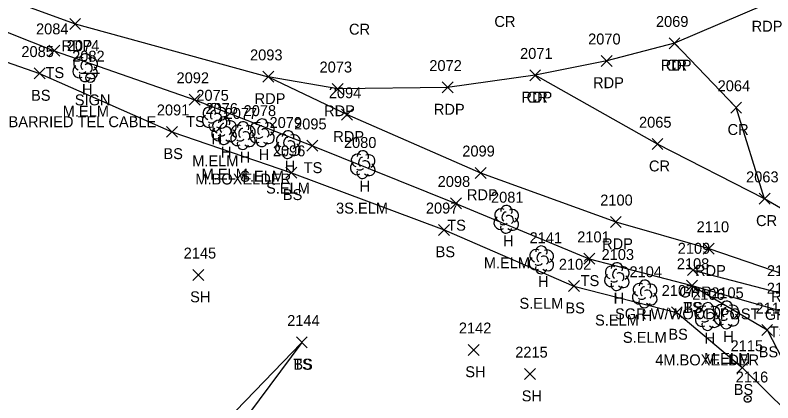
# Model space of a CAD drawing. Extents: x 1459992 to 1461532, y 647785 to 648535.
# Drawn here: x 1461117.9 to 1461256.6, y 648209.9 to 648280.9 of the extents above; entities that cross this region are included whole.
import ezdxf

# ---------------------------------------------------------------- set-up
doc = ezdxf.new("R2010")
doc.units = 0
for name, color, linetype in [('L_A', 7, 'Continuous'), ('L_C', 7, 'Continuous'), ('L_I', 7, 'Continuous'), ('L_TIC', 7, 'Continuous'), ('LELB', 7, 'Continuous'), ('LTD', 7, 'Continuous'), ('P_A', 7, 'Continuous'), ('P_I', 7, 'Continuous'), ('P_TIC', 7, 'Continuous'), ('PET', 7, 'Continuous'), ('PRC', 7, 'Continuous'), ('R_A', 7, 'Continuous'), ('R_C', 7, 'Continuous'), ('R_I', 7, 'Continuous'), ('R_TIC', 7, 'Continuous'), ('RGR', 7, 'Continuous'), ('S_A', 7, 'Continuous'), ('S_C', 7, 'Continuous'), ('S_I', 7, 'Continuous'), ('SSGN', 7, 'Continuous'), ('U_I', 7, 'Continuous'), ('UPGW', 7, 'Continuous')]:
    doc.layers.add(name, color=color, linetype=linetype)

msp = doc.modelspace()

# ---------------------------------------------------------------- linework, layer by layer
at = {"layer": 'L_TIC'}
for points in [[(1461124.02, 648273.34), (1461126.02, 648275.34)], [(1461126.02, 648273.34), (1461124.02, 648275.34)], [(1461121.33, 648269.19), (1461123.33, 648271.19)], [(1461123.33, 648269.19), (1461121.33, 648271.19)], [(1461149.75, 648264.39), (1461151.75, 648266.39)], [(1461151.75, 648264.39), (1461149.75, 648266.39)], [(1461145.57, 648258.51), (1461147.57, 648260.51)], [(1461147.57, 648258.51), (1461145.57, 648260.51)], [(1461171.28, 648255.95), (1461173.28, 648257.95)], [(1461173.28, 648255.95), (1461171.28, 648257.95)], [(1461167.44, 648251.02), (1461169.44, 648253.02)], [(1461169.44, 648251.02), (1461167.44, 648253.02)], [(1461197.57, 648245.42), (1461199.57, 648247.42)], [(1461199.57, 648245.42), (1461197.57, 648247.42)], [(1461195.41, 648240.56), (1461197.41, 648242.56)], [(1461197.41, 648240.56), (1461195.41, 648242.56)], [(1461222, 648235.28), (1461224, 648237.28)], [(1461224, 648235.28), (1461222, 648237.28)], [(1461150.42, 648232.32), (1461152.42, 648234.32)], [(1461152.42, 648232.32), (1461150.42, 648234.32)], [(1461219.18, 648230.28), (1461221.18, 648232.28)], [(1461221.18, 648230.28), (1461219.18, 648232.28)], [(1461240.79, 648230.37), (1461242.79, 648232.37)], [(1461242.79, 648230.37), (1461240.79, 648232.37)], [(1461240.79, 648230.37), (1461242.79, 648232.37)], [(1461242.79, 648230.37), (1461240.79, 648232.37)], [(1461238.03, 648225.47), (1461240.03, 648227.47)], [(1461240.03, 648225.47), (1461238.03, 648227.47)], [(1461254.57, 648222.25), (1461256.57, 648224.25)], [(1461256.57, 648222.25), (1461254.57, 648224.25)], [(1461169.36, 648219.98), (1461171.36, 648221.98)], [(1461171.36, 648219.98), (1461169.36, 648221.98)], [(1461169.36, 648219.98), (1461171.36, 648221.98)], [(1461171.36, 648219.98), (1461169.36, 648221.98)], [(1461200.8, 648218.61), (1461202.8, 648220.61)], [(1461202.8, 648218.61), (1461200.8, 648220.61)], [(1461250, 648215.36), (1461252, 648217.36)], [(1461252, 648215.36), (1461250, 648217.36)], [(1461211.13, 648214.19), (1461213.13, 648216.19)], [(1461213.13, 648214.19), (1461211.13, 648216.19)]]:
    msp.add_lwpolyline(points, dxfattribs=at)
at = {"layer": 'LELB'}
for points in [[(1460941.15, 648349.78), (1460973.92, 648337.2), (1461015.24, 648321.11), (1461040.67, 648310.01), (1461064.18, 648298.16), (1461082.22, 648291.36), (1461125.02, 648274.34), (1461150.75, 648265.39), (1461172.28, 648256.95), (1461198.57, 648246.42), (1461223, 648236.28), (1461241.79, 648231.37), (1461257.62, 648226.89), (1461266.9, 648221.63), (1461276.01, 648214.68), (1461281.47, 648211.06), (1461286.34, 648210.46)], [(1460939.64, 648344.38), (1460971.19, 648332.05), (1461013, 648314.77), (1461039.31, 648304.76), (1461062.9, 648294.47), (1461067.87, 648294.36), (1461073.92, 648287.11), (1461122.33, 648270.19), (1461146.57, 648259.51), (1461168.44, 648252.02), (1461196.41, 648241.56), (1461220.18, 648231.28), (1461239.03, 648226.47), (1461251, 648216.36), (1461259.3, 648208.22), (1461262.9, 648204.94)], [(1461241.79, 648231.37), (1461255.57, 648223.25), (1461261.15, 648212.52)], [(1461170.36, 648220.98), (1461142.74, 648192.43), (1461120.86, 648163.3), (1461094.01, 648129.04), (1461070.6, 648103.29)], [(1461170.36, 648220.98), (1461146.74, 648189.22), (1461125.11, 648160.77), (1461098.02, 648125.46), (1461077.7, 648098.65)]]:
    msp.add_lwpolyline(points, dxfattribs=at)
at = {"layer": 'LTD'}
for p, q in [((1461130.66, 648271.28), (1461130.66, 648271.28)), ((1461130.66, 648271.28), (1461130.66, 648271.28)), ((1461154.37, 648262.19), (1461154.37, 648262.19)), ((1461154.37, 648262.19), (1461154.37, 648262.19)), ((1461156.1, 648259.77), (1461156.1, 648259.77)), ((1461156.1, 648259.77), (1461156.1, 648259.77)), ((1461163.03, 648259.38), (1461163.03, 648259.38)), ((1461163.03, 648259.38), (1461163.03, 648259.38)), ((1461159.56, 648258.87), (1461159.56, 648258.87)), ((1461159.56, 648258.87), (1461159.56, 648258.87)), ((1461167.78, 648257.21), (1461167.78, 648257.21)), ((1461167.78, 648257.21), (1461167.78, 648257.21)), ((1461181.49, 648253.55), (1461181.49, 648253.55)), ((1461181.49, 648253.55), (1461181.49, 648253.55)), ((1461207.77, 648243.54), (1461207.77, 648243.54)), ((1461207.77, 648243.54), (1461207.77, 648243.54)), ((1461214.18, 648236.13), (1461214.18, 648236.13)), ((1461214.18, 648236.13), (1461214.18, 648236.13)), ((1461228.02, 648233.06), (1461228.02, 648233.06)), ((1461228.02, 648233.06), (1461228.02, 648233.06)), ((1461233.12, 648229.9), (1461233.12, 648229.9)), ((1461233.12, 648229.9), (1461233.12, 648229.9)), ((1461248.09, 648226.05), (1461248.09, 648226.05)), ((1461248.09, 648226.05), (1461248.09, 648226.05)), ((1461244.66, 648225.77), (1461244.66, 648225.77)), ((1461244.66, 648225.77), (1461244.66, 648225.77))]:
    msp.add_line(p, q, dxfattribs=at)
for centre in [(1461130.7, 648272.72), (1461154.42, 648263.63), (1461156.14, 648261.2), (1461159.61, 648260.31), (1461163.07, 648260.82), (1461167.83, 648258.65), (1461181.53, 648254.99), (1461207.82, 648244.97), (1461214.23, 648237.57), (1461228.06, 648234.49), (1461233.17, 648231.33), (1461244.71, 648227.21), (1461248.14, 648227.48)]:
    msp.add_arc(centre, 1.05, 335.5272, 180.9563, dxfattribs=at)
for centre, major_axis, ratio, start_param, end_param in [((1461129.86, 648271.95), (1.21, -0.51), 0.895232, 1.570796, 4.712389), ((1461131.7, 648271.87), (-1.14, -0.48), 0.949671, 1.570796, 4.712389), ((1461130.45, 648271.74), (-0.208, -0.792), 0.645439, 3.141593, 6.283185), ((1461131.16, 648271.12), (-0.5, 0.667), 0.989748, 3.141593, 6.283185), ((1461129.57, 648270.57), (0.58, -1.04), 0.959034, 3.141593, 6.283185), ((1461130.2, 648270.53), (-0.625, -0.083), 0.423636, 0, 3.141593), ((1461131.66, 648270.45), (-1.09, 0.79), 0.841452, 1.570796, 4.712389), ((1461130.66, 648269.78), (0.26, 1.06), 0.942809, 1.570796, 4.712389), ((1461153.58, 648262.86), (1.21, -0.51), 0.895232, 1.570796, 4.712389), ((1461154.16, 648262.65), (-0.208, -0.792), 0.645439, 3.141593, 6.283185), ((1461155.41, 648262.78), (-1.14, -0.48), 0.949671, 1.570796, 4.712389), ((1461153.29, 648261.48), (0.58, -1.04), 0.959034, 3.141593, 6.283185), ((1461154.87, 648262.03), (-0.5, 0.667), 0.989748, 3.141593, 6.283185), ((1461155.37, 648261.36), (-1.09, 0.79), 0.841452, 1.570796, 4.712389), ((1461154.37, 648260.69), (0.26, 1.06), 0.942809, 1.570796, 4.712389), ((1461153.91, 648261.44), (-0.625, -0.083), 0.423636, 0, 3.141593), ((1461155.31, 648260.43), (1.21, -0.51), 0.895232, 1.570796, 4.712389), ((1461155.89, 648260.22), (-0.208, -0.792), 0.645439, 3.141593, 6.283185), ((1461157.14, 648260.35), (-1.14, -0.48), 0.949671, 1.570796, 4.712389), ((1461158.77, 648259.54), (1.21, -0.51), 0.895232, 1.570796, 4.712389), ((1461160.6, 648259.46), (-1.14, -0.48), 0.949671, 1.570796, 4.712389), ((1461162.24, 648260.05), (1.21, -0.51), 0.895232, 1.570796, 4.712389), ((1461162.82, 648259.84), (-0.208, -0.792), 0.645439, 3.141593, 6.283185), ((1461164.07, 648259.97), (-1.14, -0.48), 0.949671, 1.570796, 4.712389), ((1461155.01, 648259.06), (0.58, -1.04), 0.959034, 3.141593, 6.283185), ((1461156.6, 648259.6), (-0.5, 0.667), 0.989748, 3.141593, 6.283185), ((1461157.1, 648258.93), (-1.09, 0.79), 0.841452, 1.570796, 4.712389), ((1461159.35, 648259.33), (-0.208, -0.792), 0.645439, 3.141593, 6.283185), ((1461160.06, 648258.71), (-0.5, 0.667), 0.989748, 3.141593, 6.283185), ((1461161.94, 648258.68), (0.58, -1.04), 0.959034, 3.141593, 6.283185), ((1461163.53, 648259.22), (-0.5, 0.667), 0.989748, 3.141593, 6.283185), ((1461164.03, 648258.55), (-1.09, 0.79), 0.841452, 1.570796, 4.712389), ((1461156.1, 648258.27), (0.26, 1.06), 0.942809, 1.570796, 4.712389), ((1461155.64, 648259.01), (-0.625, -0.083), 0.423636, 0, 3.141593), ((1461158.48, 648258.16), (0.58, -1.04), 0.959034, 3.141593, 6.283185), ((1461159.1, 648258.12), (-0.625, -0.083), 0.423636, 0, 3.141593), ((1461160.56, 648258.04), (-1.09, 0.79), 0.841452, 1.570796, 4.712389), ((1461163.03, 648257.88), (0.26, 1.06), 0.942809, 1.570796, 4.712389), ((1461162.57, 648258.63), (-0.625, -0.083), 0.423636, 0, 3.141593), ((1461166.99, 648257.88), (1.21, -0.51), 0.895232, 1.570796, 4.712389), ((1461167.57, 648257.67), (-0.208, -0.792), 0.645439, 3.141593, 6.283185), ((1461168.28, 648257.05), (-0.5, 0.667), 0.989748, 3.141593, 6.283185), ((1461168.82, 648257.8), (-1.14, -0.48), 0.949671, 1.570796, 4.712389), ((1461159.56, 648257.37), (0.26, 1.06), 0.942809, 1.570796, 4.712389), ((1461166.7, 648256.5), (0.58, -1.04), 0.959034, 3.141593, 6.283185), ((1461167.32, 648256.46), (-0.625, -0.083), 0.423636, 0, 3.141593), ((1461168.78, 648256.38), (-1.09, 0.79), 0.841452, 1.570796, 4.712389), ((1461167.78, 648255.71), (0.26, 1.06), 0.942809, 1.570796, 4.712389), ((1461180.7, 648254.22), (1.21, -0.51), 0.895232, 1.570796, 4.712389), ((1461182.53, 648254.14), (-1.14, -0.48), 0.949671, 1.570796, 4.712389), ((1461180.4, 648252.84), (0.58, -1.04), 0.959034, 3.141593, 6.283185), ((1461181.28, 648254.01), (-0.208, -0.792), 0.645439, 3.141593, 6.283185), ((1461181.99, 648253.39), (-0.5, 0.667), 0.989748, 3.141593, 6.283185), ((1461181.03, 648252.8), (-0.625, -0.083), 0.423636, 0, 3.141593), ((1461182.49, 648252.72), (-1.09, 0.79), 0.841452, 1.570796, 4.712389), ((1461181.49, 648252.05), (0.26, 1.06), 0.942809, 1.570796, 4.712389), ((1461206.98, 648244.21), (1.21, -0.51), 0.895232, 1.570796, 4.712389), ((1461208.81, 648244.12), (-1.14, -0.48), 0.949671, 1.570796, 4.712389), ((1461207.56, 648244), (-0.208, -0.792), 0.645439, 3.141593, 6.283185), ((1461208.27, 648243.37), (-0.5, 0.667), 0.989748, 3.141593, 6.283185), ((1461206.69, 648242.83), (0.58, -1.04), 0.959034, 3.141593, 6.283185), ((1461207.31, 648242.79), (-0.625, -0.083), 0.423636, 0, 3.141593), ((1461208.77, 648242.71), (-1.09, 0.79), 0.841452, 1.570796, 4.712389), ((1461207.77, 648242.04), (0.26, 1.06), 0.942809, 1.570796, 4.712389), ((1461213.39, 648236.8), (1.21, -0.51), 0.895232, 1.570796, 4.712389), ((1461213.97, 648236.59), (-0.208, -0.792), 0.645439, 3.141593, 6.283185), ((1461215.22, 648236.71), (-1.14, -0.48), 0.949671, 1.570796, 4.712389), ((1461213.1, 648235.42), (0.58, -1.04), 0.959034, 3.141593, 6.283185), ((1461214.68, 648235.96), (-0.5, 0.667), 0.989748, 3.141593, 6.283185), ((1461215.18, 648235.3), (-1.09, 0.79), 0.841452, 1.570796, 4.712389), ((1461214.18, 648234.63), (0.26, 1.06), 0.942809, 1.570796, 4.712389), ((1461213.72, 648235.38), (-0.625, -0.083), 0.423636, 0, 3.141593), ((1461227.22, 648233.73), (1.21, -0.51), 0.895232, 1.570796, 4.712389), ((1461227.81, 648233.52), (-0.208, -0.792), 0.645439, 3.141593, 6.283185), ((1461229.06, 648233.64), (-1.14, -0.48), 0.949671, 1.570796, 4.712389), ((1461226.93, 648232.35), (0.58, -1.04), 0.959034, 3.141593, 6.283185), ((1461228.52, 648232.89), (-0.5, 0.667), 0.989748, 3.141593, 6.283185), ((1461229.02, 648232.23), (-1.09, 0.79), 0.841452, 1.570796, 4.712389), ((1461228.02, 648231.56), (0.26, 1.06), 0.942809, 1.570796, 4.712389), ((1461227.56, 648232.31), (-0.625, -0.083), 0.423636, 0, 3.141593), ((1461232.33, 648230.57), (1.21, -0.51), 0.895232, 1.570796, 4.712389), ((1461234.16, 648230.48), (-1.14, -0.48), 0.949671, 1.570796, 4.712389), ((1461232.04, 648229.19), (0.58, -1.04), 0.959034, 3.141593, 6.283185), ((1461232.91, 648230.36), (-0.208, -0.792), 0.645439, 3.141593, 6.283185), ((1461233.62, 648229.73), (-0.5, 0.667), 0.989748, 3.141593, 6.283185), ((1461232.66, 648229.15), (-0.625, -0.083), 0.423636, 0, 3.141593), ((1461234.12, 648229.07), (-1.09, 0.79), 0.841452, 1.570796, 4.712389), ((1461233.12, 648228.4), (0.26, 1.06), 0.942809, 1.570796, 4.712389), ((1461243.87, 648226.44), (1.21, -0.51), 0.895232, 1.570796, 4.712389), ((1461245.71, 648226.36), (-1.14, -0.48), 0.949671, 1.570796, 4.712389), ((1461247.3, 648226.71), (1.21, -0.51), 0.895232, 1.570796, 4.712389), ((1461247.88, 648226.51), (-0.208, -0.792), 0.645439, 3.141593, 6.283185), ((1461249.13, 648226.63), (-1.14, -0.48), 0.949671, 1.570796, 4.712389), ((1461243.58, 648225.06), (0.58, -1.04), 0.959034, 3.141593, 6.283185), ((1461244.46, 648226.23), (-0.208, -0.792), 0.645439, 3.141593, 6.283185), ((1461245.16, 648225.61), (-0.5, 0.667), 0.989748, 3.141593, 6.283185), ((1461247.01, 648225.34), (0.58, -1.04), 0.959034, 3.141593, 6.283185), ((1461248.59, 648225.88), (-0.5, 0.667), 0.989748, 3.141593, 6.283185), ((1461249.09, 648225.21), (-1.09, 0.79), 0.841452, 1.570796, 4.712389), ((1461244.21, 648225.02), (-0.625, -0.083), 0.423636, 0, 3.141593), ((1461245.66, 648224.94), (-1.09, 0.79), 0.841452, 1.570796, 4.712389), ((1461248.09, 648224.55), (0.26, 1.06), 0.942809, 1.570796, 4.712389), ((1461247.63, 648225.3), (-0.625, -0.083), 0.423636, 0, 3.141593), ((1461244.66, 648224.27), (0.26, 1.06), 0.942809, 1.570796, 4.712389)]:
    msp.add_ellipse(centre, major_axis=major_axis, ratio=ratio, start_param=start_param, end_param=end_param, dxfattribs=at)
at = {"layer": 'P_TIC'}
for points in [[(1461127.85, 648278.26), (1461129.85, 648280.26)], [(1461129.85, 648278.26), (1461127.85, 648280.26)], [(1461237.6, 648274.7), (1461239.6, 648276.7)], [(1461239.6, 648274.7), (1461237.6, 648276.7)], [(1461237.6, 648274.7), (1461239.6, 648276.7)], [(1461239.6, 648274.7), (1461237.6, 648276.7)], [(1461225.2, 648271.49), (1461227.2, 648273.49)], [(1461227.2, 648271.49), (1461225.2, 648273.49)], [(1461163.21, 648268.58), (1461165.21, 648270.58)], [(1461165.21, 648268.58), (1461163.21, 648270.58)], [(1461163.21, 648268.58), (1461165.21, 648270.58)], [(1461165.21, 648268.58), (1461163.21, 648270.58)], [(1461212.09, 648268.85), (1461214.09, 648270.85)], [(1461214.09, 648268.85), (1461212.09, 648270.85)], [(1461212.09, 648268.85), (1461214.09, 648270.85)], [(1461214.09, 648268.85), (1461212.09, 648270.85)], [(1461175.94, 648266.36), (1461177.94, 648268.36)], [(1461177.94, 648266.36), (1461175.94, 648268.36)], [(1461196.04, 648266.63), (1461198.04, 648268.63)], [(1461198.04, 648266.63), (1461196.04, 648268.63)], [(1461248.89, 648262.93), (1461250.89, 648264.93)], [(1461250.89, 648262.93), (1461248.89, 648264.93)], [(1461177.63, 648261.65), (1461179.63, 648263.65)], [(1461179.63, 648261.65), (1461177.63, 648263.65)], [(1461234.48, 648256.26), (1461236.48, 648258.26)], [(1461236.48, 648256.26), (1461234.48, 648258.26)], [(1461202.09, 648250.99), (1461204.09, 648252.99)], [(1461204.09, 648250.99), (1461202.09, 648252.99)], [(1461254.1, 648246.26), (1461256.1, 648248.26)], [(1461256.1, 648246.26), (1461254.1, 648248.26)], [(1461254.1, 648246.26), (1461256.1, 648248.26)], [(1461256.1, 648246.26), (1461254.1, 648248.26)], [(1461226.86, 648242.02), (1461228.86, 648244.02)], [(1461228.86, 648242.02), (1461226.86, 648244.02)], [(1461243.86, 648237.13), (1461245.86, 648239.13)], [(1461245.86, 648237.13), (1461243.86, 648239.13)]]:
    msp.add_lwpolyline(points, dxfattribs=at)
at = {"layer": 'PET'}
for points in [[(1461431.71, 648423.56), (1461406.61, 648408.47), (1461395.32, 648400.74), (1461379.71, 648387.97), (1461360, 648370.89), (1461342.5, 648355.32), (1461322.76, 648336.16), (1461306.54, 648318.18), (1461292.23, 648305.65), (1461275.7, 648293.86), (1461255.23, 648282.83), (1461238.6, 648275.7), (1461226.2, 648272.49), (1461213.09, 648269.85), (1461197.04, 648267.63), (1461176.94, 648267.36), (1461164.21, 648269.58)], [(1460942.85, 648353.98), (1460975.34, 648340.07), (1461016.08, 648323.29), (1461041.44, 648312.66), (1461070.03, 648301.09), (1461083.95, 648295.62), (1461128.85, 648279.26), (1461164.21, 648269.58), (1461178.63, 648262.65), (1461203.09, 648251.99), (1461227.86, 648243.02), (1461244.86, 648238.13), (1461258.8, 648233.38), (1461270.23, 648226.19), (1461279.65, 648219.62), (1461287.61, 648211.81)]]:
    msp.add_lwpolyline(points, dxfattribs=at)
at = {"layer": 'PRC'}
for points in [[(1461255.1, 648247.26), (1461249.89, 648263.93), (1461238.6, 648275.7)], [(1461267.85, 648239.79), (1461255.1, 648247.26), (1461235.48, 648257.26), (1461213.09, 648269.85)]]:
    msp.add_lwpolyline(points, dxfattribs=at)
at = {"layer": 'R_TIC'}
for points in [[(1461240.97, 648233.2), (1461242.97, 648235.2)], [(1461242.97, 648233.2), (1461240.97, 648235.2)]]:
    msp.add_lwpolyline(points, dxfattribs=at)
at = {"layer": 'RGR'}
msp.add_lwpolyline([(1461241.97, 648234.2), (1461257.65, 648230.1), (1461269.1, 648224.37), (1461278.11, 648218.35), (1461287.31, 648211.6)], dxfattribs=at)
at = {"layer": 'SSGN'}
for p, q in [((1461130, 648270.21), (1461133.33, 648270.21)), ((1461131.64, 648269.38), (1461131.64, 648269.38))]:
    msp.add_line(p, q, dxfattribs=at)
msp.add_circle((1461131.64, 648269.38), 0.833, dxfattribs=at)
at = {"layer": 'UPGW'}
for radius in [0.625, 0.0833]:
    msp.add_circle((1461251.99, 648210.64), radius, dxfattribs=at)

# ---------------------------------------------------------------- texts
at = {"layer": 'L_A'}
for s, p in [('TS', (1461123.42, 648269.34)), ('H', (1461130.09, 648266.28)), ('BS', (1461120.77, 648265.19)), ('TS', (1461149.16, 648260.39)), ('H', (1461153.81, 648257.19)), ('BS', (1461145.01, 648254.51)), ('H', (1461155.53, 648254.77)), ('H', (1461158.99, 648253.87)), ('H', (1461162.46, 648254.38)), ('H', (1461167.21, 648252.21)), ('TS', (1461170.69, 648251.95)), ('H', (1461180.92, 648248.55)), ('BS', (1461166.88, 648247.02)), ('TS', (1461196.98, 648241.42)), ('H', (1461207.2, 648238.54)), ('BS', (1461194.85, 648236.56)), ('H', (1461213.62, 648231.13)), ('TS', (1461221.41, 648231.28)), ('SH', (1461149.9, 648228.32)), ('H', (1461227.45, 648228.06)), ('BS', (1461218.62, 648226.28)), ('TS', (1461240.2, 648226.37)), ('BS', (1461240.23, 648226.37)), ('H', (1461232.56, 648224.9)), ('BS', (1461237.47, 648221.47)), ('TS', (1461256.03, 648221.89)), ('H', (1461244.1, 648220.77)), ('H', (1461247.52, 648221.05)), ('BS', (1461254.01, 648218.25)), ('TS', (1461168.77, 648215.98)), ('BS', (1461168.8, 648215.98)), ('SH', (1461200.29, 648214.61)), ('SH', (1461210.62, 648210.19)), ('BS', (1461249.44, 648211.36))]:
    msp.add_text(s, height=2, dxfattribs=at).set_placement(p)
at = {"layer": 'L_C'}
for s, p in [('M.ELM', (1461126.56, 648262.28)), ('M.ELM', (1461150.28, 648253.19)), ('M.ELM', (1461152, 648250.77)), ('S.ELM', (1461159.06, 648250.38)), ('M.BOXELDER', (1461150.86, 648249.87)), ('S.ELM', (1461163.81, 648248.21)), ('3S.ELM', (1461176.62, 648244.55)), ('M.ELM', (1461203.68, 648234.54)), ('S.ELM', (1461210.21, 648227.13)), ('S.ELM', (1461224.05, 648224.06)), ('S.ELM', (1461229.15, 648220.9)), ('M.ELM', (1461244, 648217.05)), ('4M.BOXELDER', (1461235.07, 648216.77))]:
    msp.add_text(s, height=2, dxfattribs=at).set_placement(p)
at = {"layer": 'L_I'}
for s, p in [('2084', (1461121.68, 648277.34)), ('2074', (1461127.32, 648274.28)), ('2085', (1461119, 648273.19)), ('2092', (1461147.41, 648268.39)), ('2075', (1461151.03, 648265.19)), ('2091', (1461143.8, 648262.51)), ('2076', (1461152.7, 648262.77)), ('2077', (1461156.22, 648261.87)), ('2078', (1461159.69, 648262.38)), ('2079', (1461164.44, 648260.21)), ('2095', (1461168.94, 648259.95)), ('2080', (1461178.06, 648256.55)), ('2096', (1461165.04, 648255.02)), ('2098', (1461195.23, 648249.42)), ('2081', (1461205, 648246.54)), ('2097', (1461193.07, 648244.56)), ('2101', (1461220.79, 648239.28)), ('2141', (1461212.06, 648239.13)), ('2145', (1461148.72, 648236.32)), ('2103', (1461225.24, 648236.06)), ('2102', (1461217.41, 648234.28)), ('2108', (1461239.02, 648234.37)), ('2108', (1461239.02, 648234.37)), ('2104', (1461230.35, 648232.9)), ('2113', (1461255.5, 648229.89)), ('2107', (1461236.25, 648229.47)), ('2106', (1461241.84, 648228.77)), ('2105', (1461245.32, 648229.05)), ('2114', (1461253.44, 648226.25)), ('2144', (1461167.67, 648223.98)), ('2144', (1461167.67, 648223.98)), ('2142', (1461199.11, 648222.61)), ('2115', (1461248.87, 648219.36)), ('2215', (1461209.43, 648218.19))]:
    msp.add_text(s, height=2, dxfattribs=at).set_placement(p)
at = {"layer": 'P_A'}
for s, p in [('CR', (1461205.61, 648278.7)), ('CR', (1461178.99, 648277.29)), ('RDP', (1461252.72, 648277.83)), ('RDP', (1461126.34, 648274.26)), ('RDP', (1461236.08, 648270.7)), ('CR', (1461237.03, 648270.7)), ('RDP', (1461223.69, 648267.49)), ('RDP', (1461161.7, 648264.58)), ('RDP', (1461161.7, 648264.58)), ('RDP', (1461210.57, 648264.85)), ('CR', (1461211.52, 648264.85)), ('RDP', (1461174.43, 648262.36)), ('RDP', (1461194.53, 648262.63)), ('CR', (1461248.32, 648258.93)), ('RDP', (1461176.11, 648257.65)), ('CR', (1461233.92, 648252.26)), ('RDP', (1461200.58, 648246.99)), ('CR', (1461253.53, 648242.26)), ('CR', (1461253.53, 648242.26)), ('RDP', (1461225.34, 648238.02)), ('RDP', (1461242.35, 648233.13)), ('RDP', (1461256.29, 648228.38))]:
    msp.add_text(s, height=2, dxfattribs=at).set_placement(p)
at = {"layer": 'P_I'}
for s, p in [('2069', (1461235.2, 648278.7)), ('2069', (1461235.2, 648278.7)), ('2070', (1461222.78, 648275.49)), ('2093', (1461160.87, 648272.58)), ('2093', (1461160.87, 648272.58)), ('2071', (1461210.32, 648272.85)), ('2071', (1461210.32, 648272.85)), ('2073', (1461173.6, 648270.36)), ('2072', (1461193.7, 648270.63)), ('2094', (1461175.29, 648265.65)), ('2064', (1461246.5, 648266.93)), ('2065', (1461232.1, 648260.26)), ('2099', (1461199.74, 648254.99)), ('2063', (1461251.71, 648250.26)), ('2063', (1461251.71, 648250.26)), ('2100', (1461225, 648246.02)), ('2110', (1461242.65, 648241.13))]:
    msp.add_text(s, height=2, dxfattribs=at).set_placement(p)
at = {"layer": 'R_A'}
for p in [(1461239.46, 648229.2), (1461255.14, 648225.1)]:
    msp.add_text('GRR', height=2, dxfattribs=at).set_placement(p)
at = {"layer": 'R_C'}
msp.add_text('SGR W/WOOD POST', height=2, dxfattribs=at).set_placement((1461227.71, 648225.2))
at = {"layer": 'R_I'}
for s, p in [('2109', (1461239.19, 648237.2)), ('2112', (1461255.53, 648233.1))]:
    msp.add_text(s, height=2, dxfattribs=at).set_placement(p)
at = {"layer": 'S_A'}
msp.add_text('SIGN', height=2, dxfattribs=at).set_placement((1461128.78, 648264.35))
at = {"layer": 'S_C'}
msp.add_text('BARRIED TEL CABLE', height=2, dxfattribs=at).set_placement((1461116.65, 648260.35))
at = {"layer": 'S_I'}
msp.add_text('2082', height=2, dxfattribs=at).set_placement((1461128.29, 648272.35))
at = {"layer": 'U_I'}
msp.add_text('2116', height=2, dxfattribs=at).set_placement((1461249.81, 648213.64))

doc.saveas('drawing.dxf')
